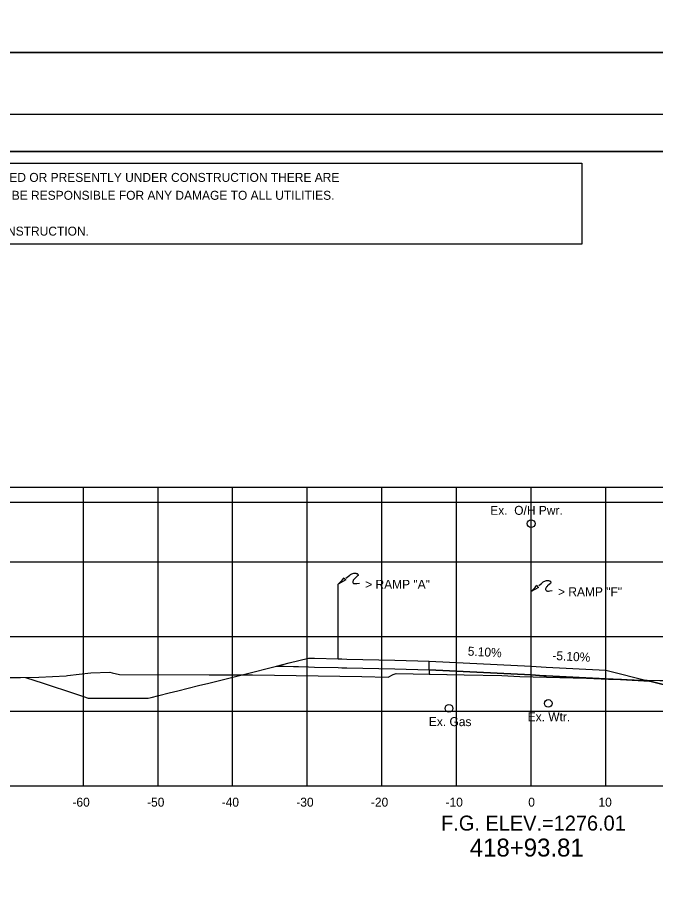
# Model space of a CAD drawing. Extents: x 2148105 to 2149976, y 144169 to 149705.
# Drawn here: x 2148344.5 to 2148430, y 149113.3 to 149229.9 of the extents above; entities that cross this region are included whole.
import ezdxf

# ---------------------------------------------------------------- set-up
doc = ezdxf.new("R2010")
doc.units = 0
for name, color, linetype in [('Bridge M-Header', 7, 'Continuous'), ('Default', 7, 'Continuous'), ('INR_Tracking', 7, 'Continuous'), ('PH1a-PR-ServRd', 7, 'Continuous'), ('PH2-PR-Barrier', 7, 'Continuous'), ('PR-AttenuatorPad', 7, 'Continuous'), ('PR_Align_Ramp_E', 7, 'Continuous'), ('PR_Align_Ramp_J', 7, 'Continuous'), ('PR_Storm_Channel', 7, 'Continuous'), ('PR_Storm_Conc_Box_PH1B', 7, 'Continuous'), ('PR_Storm_Conc_Pipe', 7, 'Continuous'), ('PR_Storm_Conc_Pipe_PH1B', 7, 'Continuous'), ('PR_Storm_Inlet_CICI_PH1B', 7, 'Continuous'), ('PR_Storm_Junction_Box_PH1A', 7, 'Continuous'), ('PR_Storm_Junction_Box_PH1B', 7, 'Continuous'), ('PR_Storm_MH', 7, 'Continuous'), ('PR_Storm_MH_PH1B', 7, 'Continuous'), ('PR_Storm_Standard_Median_Drain_PH1B', 7, 'Continuous'), ('PR_Storm_Txt_PH1B', 7, 'Continuous'), ('TopCut', 7, 'Continuous'), ('TOPO_Asphalt', 7, 'Continuous'), ('TOPO_BRIDGE_Pier Cap', 7, 'Continuous')]:
    doc.layers.add(name, color=color, linetype=linetype)

# ---------------------------------------------------------------- blocks, each defined once
blk = doc.blocks.new('POINT_DISPLAY')
at = {"layer": 'Default'}
blk.add_line((0, 0), (0, 0), dxfattribs=at)

msp = doc.modelspace()

# ---------------------------------------------------------------- linework, layer by layer
at = {"layer": 'INR_Tracking'}
msp.add_lwpolyline([(2148399.67, 149142.45), (2148413.32, 149141.75), (2148415.03, 149141.66), (2148415.32, 149141.65), (2148423.31, 149141.24), (2148423.32, 149141.24), (2148425.31, 149141.14), (2148425.31, 149141.14), (2148425.32, 149141.14), (2148429.19, 149140.94), (2148429.21, 149140.93), (2148436.2, 149139.19), (2148436.21, 149139.19), (2148444.2, 149139.19), (2148480.7, 149147.69), (2148512.85, 149155.19)], dxfattribs=at)
at = {"layer": 'PH1a-PR-ServRd'}
msp.add_lwpolyline([(2148570.82, 149001.91), (2148255.82, 149001.91), (2148255.82, 149211.91), (2148570.82, 149211.91)], close=True, dxfattribs=at)
at = {"layer": 'PH2-PR-Barrier'}
msp.add_line((2148413.32, 149142.92), (2148413.32, 149152.92), dxfattribs=at)
for points in [[(2148413.32, 149152.92), (2148413.84, 149153.47), (2148414.1, 149153.77), (2148414.18, 149153.61), (2148414.32, 149153.49), (2148413.32, 149152.92)], [(2148414.33, 149153.73), (2148414.69, 149154.02), (2148414.85, 149154.15), (2148414.94, 149154.22), (2148415.04, 149154.28), (2148415.14, 149154.32), (2148415.26, 149154.36), (2148415.39, 149154.39), (2148415.49, 149154.4), (2148415.57, 149154.4), (2148415.65, 149154.39), (2148415.72, 149154.38), (2148415.78, 149154.37), (2148415.83, 149154.35), (2148415.87, 149154.32), (2148415.91, 149154.29), (2148415.95, 149154.24), (2148415.98, 149154.19), (2148415.97, 149154.13), (2148415.96, 149154.09), (2148415.91, 149154.02), (2148415.72, 149153.86), (2148415.53, 149153.7), (2148415.46, 149153.62), (2148415.39, 149153.55), (2148415.33, 149153.45), (2148415.29, 149153.39), (2148415.25, 149153.3), (2148415.25, 149153.22), (2148415.27, 149153.14), (2148415.31, 149153.07), (2148415.36, 149153.04), (2148415.42, 149153.01), (2148415.53, 149153), (2148415.66, 149153), (2148415.82, 149153.02), (2148416.15, 149153.06)]]:
    msp.add_lwpolyline(points, dxfattribs=at)
at = {"layer": 'PR-AttenuatorPad'}
msp.add_line((2148387.48, 149143.91), (2148387.48, 149153.91), dxfattribs=at)
for points in [[(2148387.48, 149153.91), (2148388, 149154.46), (2148388.26, 149154.77), (2148388.34, 149154.6), (2148388.48, 149154.49), (2148387.48, 149153.91)], [(2148388.49, 149154.72), (2148388.84, 149155.01), (2148389.01, 149155.14), (2148389.1, 149155.22), (2148389.2, 149155.27), (2148389.3, 149155.32), (2148389.42, 149155.36), (2148389.55, 149155.39), (2148389.65, 149155.4), (2148389.73, 149155.4), (2148389.81, 149155.39), (2148389.88, 149155.37), (2148389.94, 149155.36), (2148389.99, 149155.34), (2148390.03, 149155.31), (2148390.07, 149155.28), (2148390.11, 149155.24), (2148390.14, 149155.18), (2148390.13, 149155.12), (2148390.12, 149155.08), (2148390.07, 149155.02), (2148389.88, 149154.85), (2148389.69, 149154.69), (2148389.62, 149154.61), (2148389.55, 149154.54), (2148389.49, 149154.45), (2148389.45, 149154.38), (2148389.41, 149154.29), (2148389.41, 149154.22), (2148389.43, 149154.13), (2148389.47, 149154.06), (2148389.52, 149154.03), (2148389.58, 149154.01), (2148389.69, 149153.99), (2148389.82, 149154), (2148389.98, 149154.01), (2148390.31, 149154.05)]]:
    msp.add_lwpolyline(points, dxfattribs=at)
at = {"layer": 'PR_Align_Ramp_E'}
for points in [[(2148219.95, 149465.16), (2148579.95, 149465.16), (2148579.95, 149225.16), (2148219.95, 149225.16)], [(2148219.95, 149225.16), (2148579.95, 149225.16), (2148579.95, 148985.16), (2148219.95, 148985.16)]]:
    msp.add_lwpolyline(points, close=True, dxfattribs=at)
at = {"layer": 'PR_Align_Ramp_J'}
msp.add_lwpolyline([(2148236.32, 149216.91), (2148576.32, 149216.91), (2148576.32, 148996.91), (2148236.32, 148996.91)], close=True, dxfattribs=at)
at = {"layer": 'PR_Storm_Channel'}
msp.add_lwpolyline([(2148399.67, 149143.61), (2148413.32, 149142.92), (2148415.32, 149142.81), (2148423.32, 149142.41), (2148429.19, 149140.94)], dxfattribs=at)
at = {"layer": 'PR_Storm_Conc_Box_PH1B'}
for p, q in [((2148263.32, 149166.91), (2148563.32, 149166.91)), ((2148353.32, 149126.91), (2148353.32, 149166.91)), ((2148363.32, 149126.91), (2148363.32, 149166.91)), ((2148373.32, 149126.91), (2148373.32, 149166.91)), ((2148383.32, 149126.91), (2148383.32, 149166.91)), ((2148393.32, 149126.91), (2148393.32, 149166.91)), ((2148403.32, 149126.91), (2148403.32, 149166.91)), ((2148413.32, 149126.91), (2148413.32, 149166.91)), ((2148423.32, 149126.91), (2148423.32, 149166.91)), ((2148263.32, 149156.91), (2148563.32, 149156.91)), ((2148263.32, 149146.91), (2148563.32, 149146.91)), ((2148263.32, 149136.91), (2148563.32, 149136.91)), ((2148263.32, 149126.91), (2148563.32, 149126.91))]:
    msp.add_line(p, q, dxfattribs=at)
at = {"layer": 'PR_Storm_Conc_Pipe'}
for points in [[(2148399.67, 149142.45), (2148399.67, 149142.78), (2148399.67, 149143.61)], [(2148345.58, 149141.43), (2148347.94, 149140.64), (2148352.26, 149139.21), (2148353.32, 149138.86), (2148353.96, 149138.65), (2148356.68, 149138.65), (2148357.98, 149138.65), (2148359.79, 149138.65), (2148362, 149138.65), (2148362.39, 149138.75), (2148363.44, 149139.01), (2148364.79, 149139.35), (2148365.96, 149139.64), (2148368.72, 149140.33), (2148370.11, 149140.67), (2148374.94, 149141.88), (2148379.21, 149142.94), (2148380.2, 149142.92), (2148381.48, 149142.89), (2148382.13, 149142.87), (2148383.48, 149142.84), (2148384.3, 149142.82), (2148387.48, 149142.74), (2148387.96, 149142.73), (2148388.62, 149142.72), (2148395.07, 149142.56), (2148399.67, 149142.45)]]:
    msp.add_lwpolyline(points, dxfattribs=at)
at = {"layer": 'PR_Storm_Conc_Pipe_PH1B'}
msp.add_lwpolyline([(2148255.82, 149001.91), (2148570.82, 149001.91), (2148570.82, 149211.91), (2148255.82, 149211.91)], close=True, dxfattribs=at)
msp.add_lwpolyline([(2148255.82, 149001.91), (2148570.82, 149001.91), (2148570.82, 149211.91), (2148255.82, 149211.91)], close=True, dxfattribs=at)
at = {"layer": 'PR_Storm_Inlet_CICI_PH1B'}
msp.add_lwpolyline([(2148342.81, 149141.4), (2148344.89, 149141.42), (2148347.33, 149141.45), (2148351.02, 149141.65), (2148351.19, 149141.67), (2148354.31, 149142.05), (2148356.87, 149142.14), (2148357.18, 149142.02), (2148358.14, 149141.82), (2148370.18, 149141.79), (2148375.98, 149141.78), (2148390.63, 149141.54), (2148394.15, 149141.47), (2148394.84, 149141.81), (2148395.21, 149141.96), (2148404.35, 149141.75), (2148409.39, 149141.67), (2148411.81, 149141.55), (2148420.74, 149141.32), (2148423.7, 149141.17), (2148446.09, 149140.63)], dxfattribs=at)
at = {"layer": 'PR_Storm_Junction_Box_PH1A'}
for centre in [(2148413.32, 149162.03), (2148415.61, 149137.94), (2148402.31, 149137.28)]:
    msp.add_circle(centre, 0.516, dxfattribs=at)
at = {"layer": 'PR_Storm_MH'}
msp.add_lwpolyline([(2148257.69, 149210.34), (2148420.12, 149210.34), (2148420.12, 149199.47), (2148257.69, 149199.47)], close=True, dxfattribs=at)
at = {"layer": 'PR_Storm_Standard_Median_Drain_PH1B'}
msp.add_line((2148263.32, 149126.91), (2148563.32, 149126.91), dxfattribs=at)
at = {"layer": 'PR_Storm_Txt_PH1B'}
msp.add_lwpolyline([(2148379.21, 149142.94), (2148380.9, 149143.36), (2148383.48, 149144.01), (2148384.3, 149143.99), (2148387.48, 149143.91), (2148387.95, 149143.9), (2148388.61, 149143.88), (2148395.07, 149143.73), (2148399.67, 149143.61)], dxfattribs=at)
at = {"layer": 'TopCut'}
msp.add_lwpolyline([(2148399.67, 149142.45), (2148399.67, 149141.86), (2148404.35, 149141.75), (2148409.39, 149141.67), (2148411.81, 149141.55), (2148420.74, 149141.32), (2148423.7, 149141.17), (2148425.41, 149141.13), (2148425.32, 149141.14), (2148425.31, 149141.14), (2148425.31, 149141.14), (2148423.32, 149141.24), (2148423.31, 149141.24), (2148415.32, 149141.65), (2148415.03, 149141.66), (2148413.32, 149141.75)], close=True, dxfattribs=at)
at = {"layer": 'TOPO_Asphalt'}
msp.add_line((2148263.32, 149164.91), (2148563.32, 149164.91), dxfattribs=at)
at = {"layer": 'TOPO_BRIDGE_Pier Cap'}
msp.add_lwpolyline([(2148425.41, 149141.13), (2148430.56, 149141.02), (2148430.92, 149141.01), (2148431.16, 149141.01), (2148431.84, 149140.99), (2148432.61, 149140.97), (2148433.49, 149140.95), (2148434.51, 149140.93), (2148435.7, 149140.9), (2148437.12, 149140.87), (2148438.82, 149140.83), (2148439.25, 149140.82), (2148440.9, 149140.78), (2148443.52, 149140.72), (2148446.9, 149140.64), (2148450.12, 149140.57), (2148444.2, 149139.19), (2148436.21, 149139.19), (2148436.2, 149139.19), (2148429.21, 149140.93), (2148429.19, 149140.94)], close=True, dxfattribs=at)

# ---------------------------------------------------------------- block references
at = {"layer": 'PR_Storm_Conc_Pipe_PH1B', "xscale": 10, "yscale": 10}
for p in [(2148399.67, 149143.61), (2148399.67, 149143.61), (2148415.32, 149142.81), (2148415.32, 149142.81), (2148423.32, 149142.41), (2148423.32, 149142.41)]:
    msp.add_blockref('POINT_DISPLAY', p, dxfattribs=at)

# ---------------------------------------------------------------- texts
at = {"layer": 'Bridge M-Header'}
for s, p in [('5.10%', (2148404.8, 149144.35)), ('-5.10%', (2148416.14, 149143.77))]:
    msp.add_text(s, height=1.2, rotation=357.0804, dxfattribs=at).set_placement(p)
at = {"layer": 'PH2-PR-Barrier'}
msp.add_text('> RAMP "F"', height=1.2, rotation=360, dxfattribs=at).set_placement((2148416.92, 149152.31))
at = {"layer": 'PR-AttenuatorPad'}
msp.add_text('> RAMP "A"', height=1.2, rotation=360, dxfattribs=at).set_placement((2148391.08, 149153.3))
at = {"layer": 'PR_Storm_Junction_Box_PH1A'}
for s, p in [('Ex.  O/H Pwr.', (2148407.84, 149163.21)), ('Ex. Gas', (2148399.61, 149134.9)), ('Ex. Wtr.', (2148412.85, 149135.55))]:
    msp.add_text(s, height=1.2, rotation=360, dxfattribs=at).set_placement(p)
at = {"layer": 'PR_Storm_Junction_Box_PH1B'}
msp.add_text('418+93.81', height=2.4, dxfattribs=at).set_placement((2148405.1, 149117.43))
at = {"layer": 'PR_Storm_MH'}
for s, p in [("(CAUTION) THE LOCATION OF ALL UTILITIES AS SHOWN ARE APPROXIMATE. DUE TO RELOCATION'S PLANNED OR PRESENTLY UNDER CONSTRUCTION THERE ARE ", (2148258.92, 149207.82)), ('SOME UTILITIES THAT WILL BE RELOCATED AND NOT SHOWN ON THESE PLANS. THE CONTRACTOR SHALL BE RESPONSIBLE FOR ANY DAMAGE TO ALL UTILITIES.', (2148258.92, 149205.42)), ('DEPTH & LOCATION OF EXISTING UTILITIES SHALL BE FIELD VERIFIED BY THE CONTRACTOR PRIOR TO CONSTRUCTION.', (2148258.92, 149200.62))]:
    msp.add_text(s, height=1.2, dxfattribs=at).set_placement(p)
at = {"layer": 'PR_Storm_MH_PH1B'}
for s, height, p in [('-60', 1.2, (2148351.85, 149124.11)), ('-50', 1.2, (2148361.85, 149124.11)), ('-40', 1.2, (2148371.85, 149124.11)), ('-30', 1.2, (2148381.85, 149124.11)), ('-20', 1.2, (2148391.85, 149124.11)), ('-10', 1.2, (2148401.85, 149124.11)), ('0', 1.2, (2148412.93, 149124.11)), ('10', 1.2, (2148422.34, 149124.11)), ('F.G. ELEV.=1276.01', 2, (2148401.25, 149120.91))]:
    msp.add_text(s, height=height, dxfattribs=at).set_placement(p)

doc.saveas('drawing.dxf')
